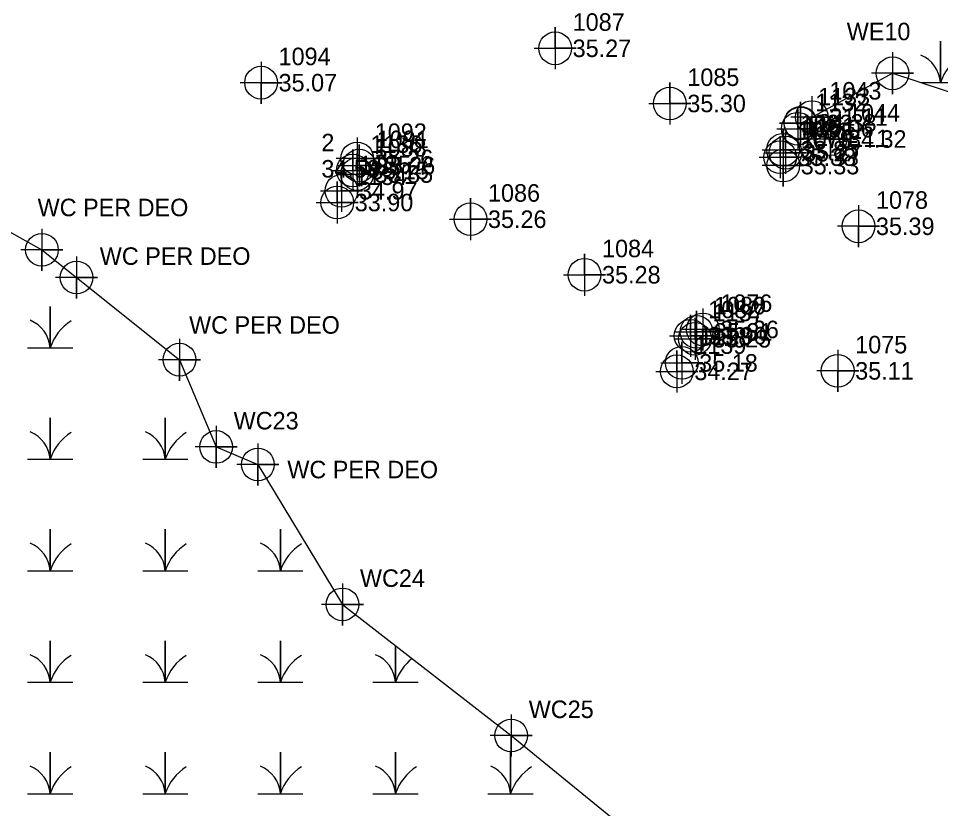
# Model space of a CAD drawing. Extents: x 2138832 to 2141061, y 149156 to 150675.
# Drawn here: x 2140515.2 to 2140647, y 149336.8 to 149449.6 of the extents above; entities that cross this region are included whole.
import ezdxf

# ---------------------------------------------------------------- set-up
doc = ezdxf.new("R2010")
doc.units = 0
for name, color, linetype in [('CTL Secondary Horizontal and Vertical Cogo Elevation', 7, 'Continuous'), ('CTL Secondary Horizontal and Vertical Cogo Number', 7, 'Continuous'), ('Exist Environmental Wetland Boundary', 7, 'Continuous'), ('Exist Environmental Wetland Boundary Cogo Number', 7, 'Continuous'), ('Exist Environmental Wetland Boundary Cogo Point CELL', 7, 'Continuous'), ('Exist Roads EOP Cogo Elevation', 7, 'Continuous'), ('Exist Roads EOP Cogo Number', 7, 'Continuous'), ('Exist Roads EOP Cogo Point CELL', 7, 'Continuous'), ('Exist Structure Major Bridge Seam Cogo Elevation', 7, 'Continuous'), ('Exist Structure Major Bridge Seam Cogo Number', 7, 'Continuous'), ('Exist Structure Major Bridge Seam Cogo Point CELL', 7, 'Continuous'), ('Exist Structure Major Bridge Seat Cogo Elevation', 7, 'Continuous'), ('Exist Structure Major Bridge Seat Cogo Number', 7, 'Continuous'), ('Exist Structure Major Bridge Seat Cogo Point CELL', 7, 'Continuous'), ('Exist Structure Major Bridge WW Cogo Elevation', 7, 'Continuous'), ('Exist Structure Major Bridge WW Cogo Number', 7, 'Continuous'), ('Exist Structure Major Bridge WW Cogo Point CELL', 7, 'Continuous'), ('Exist Structure Major Deck Tunnel Box Culvert Cogo Elevation', 7, 'Continuous'), ('Exist Structure Major Deck Tunnel Box Culvert Cogo Number', 7, 'Continuous'), ('Exist Structure Major Deck Tunnel Box Culvert Cogo Point CELL', 7, 'Continuous'), ('Exist Utilities Telephone UG FO SUE LOS C Cogo Elevation', 7, 'Continuous'), ('Exist Utilities Telephone UG FO SUE LOS C Cogo Number', 7, 'Continuous'), ('Exist Utilities Telephone UG FO SUE LOS C Cogo Point CELL', 7, 'Continuous')]:
    doc.layers.add(name, color=color, linetype=linetype)

msp = doc.modelspace()

# ---------------------------------------------------------------- linework, layer by layer
at = {"layer": 'Exist Environmental Wetland Boundary'}
msp.add_line((2140523.47, 149412.6), (2140538.17, 149400.87), dxfattribs=at)
for points in [[(2140462.13, 149440.8), (2140503.18, 149425.15), (2140518.52, 149416.56), (2140523.47, 149412.6)], [(2140626.92, 149434.6), (2140640.09, 149441.77), (2140665.85, 149433.31), (2140691.67, 149415.77), (2140722.53, 149397.21), (2140775.79, 149382.91), (2140815.44, 149353.55), (2140873.49, 149322.65), (2140932.75, 149291.76), (2140974.9, 149268.42), (2141022.6, 149236.76)], [(2140538.17, 149400.87), (2140543.42, 149388.41), (2140549.38, 149385.9)], [(2140549.38, 149385.9), (2140561.47, 149365.92)], [(2140561.47, 149365.92), (2140585.59, 149347.19)], [(2140585.59, 149347.19), (2140617.17, 149321.45), (2140653.35, 149309.39)]]:
    msp.add_lwpolyline(points, dxfattribs=at)
at = {"layer": 'Exist Environmental Wetland Boundary Cogo Point CELL'}
for points in [[(2140644.13, 149440.44), (2140646.95, 149440.44), (2140646.95, 149446.36), (2140646.95, 149440.44), (2140650.18, 149440.44)], [(2140640.09, 149444.77), (2140640.09, 149438.77), (2140640.09, 149441.77), (2140643.09, 149441.77), (2140637.09, 149441.77)], [(2140626.92, 149437.6), (2140626.92, 149431.6), (2140626.92, 149434.6), (2140629.92, 149434.6), (2140623.92, 149434.6)], [(2140518.52, 149419.56), (2140518.52, 149413.56), (2140518.52, 149416.56), (2140521.52, 149416.56), (2140515.52, 149416.56)], [(2140523.47, 149415.6), (2140523.47, 149409.6), (2140523.47, 149412.6), (2140526.47, 149412.6), (2140520.47, 149412.6)], [(2140516.47, 149402.56), (2140519.69, 149402.56), (2140519.69, 149408.48), (2140519.69, 149402.56), (2140522.92, 149402.56)], [(2140538.17, 149403.87), (2140538.17, 149397.87), (2140538.17, 149400.87), (2140541.17, 149400.87), (2140535.17, 149400.87)], [(2140516.47, 149386.65), (2140519.69, 149386.65), (2140519.69, 149392.56), (2140519.69, 149386.65), (2140522.92, 149386.65)], [(2140532.92, 149386.65), (2140536.14, 149386.65), (2140536.14, 149392.56), (2140536.14, 149386.65), (2140539.37, 149386.65)], [(2140543.42, 149391.41), (2140543.42, 149385.41), (2140543.42, 149388.41), (2140546.42, 149388.41), (2140540.42, 149388.41)], [(2140549.38, 149388.9), (2140549.38, 149382.9), (2140549.38, 149385.9), (2140552.38, 149385.9), (2140546.38, 149385.9)], [(2140516.47, 149370.73), (2140519.69, 149370.73), (2140519.69, 149376.65), (2140519.69, 149370.73), (2140522.92, 149370.73)], [(2140532.92, 149370.73), (2140536.14, 149370.73), (2140536.14, 149376.65), (2140536.14, 149370.73), (2140539.37, 149370.73)], [(2140549.37, 149370.73), (2140552.6, 149370.73), (2140552.6, 149376.65), (2140552.6, 149370.73), (2140555.82, 149370.73)], [(2140561.47, 149368.92), (2140561.47, 149362.92), (2140561.47, 149365.92), (2140564.47, 149365.92), (2140558.47, 149365.92)], [(2140516.47, 149354.81), (2140519.69, 149354.81), (2140519.69, 149360.73), (2140519.69, 149354.81), (2140522.92, 149354.81)], [(2140532.92, 149354.81), (2140536.14, 149354.81), (2140536.14, 149360.73), (2140536.14, 149354.81), (2140539.37, 149354.81)], [(2140549.37, 149354.81), (2140552.6, 149354.81), (2140552.6, 149360.73), (2140552.6, 149354.81), (2140555.82, 149354.81)], [(2140565.82, 149354.81), (2140569.05, 149354.81), (2140569.05, 149360.04)], [(2140569.05, 149360.04), (2140569.05, 149354.81), (2140572.27, 149354.81)], [(2140585.59, 149350.19), (2140585.59, 149344.19), (2140585.59, 149347.19), (2140588.59, 149347.19), (2140582.59, 149347.19)], [(2140516.47, 149338.89), (2140519.69, 149338.89), (2140519.69, 149344.81), (2140519.69, 149338.89), (2140522.92, 149338.89)], [(2140532.92, 149338.89), (2140536.14, 149338.89), (2140536.14, 149344.81), (2140536.14, 149338.89), (2140539.37, 149338.89)], [(2140549.37, 149338.89), (2140552.6, 149338.89), (2140552.6, 149344.81), (2140552.6, 149338.89), (2140555.82, 149338.89)], [(2140565.82, 149338.89), (2140569.05, 149338.89), (2140569.05, 149344.81), (2140569.05, 149338.89), (2140572.27, 149338.89)], [(2140582.27, 149338.89), (2140585.5, 149338.89), (2140585.5, 149344.81), (2140585.5, 149338.89), (2140588.72, 149338.89)]]:
    msp.add_lwpolyline(points, dxfattribs=at)
for centre in [(2140640.09, 149441.77), (2140626.92, 149434.6), (2140518.52, 149416.56), (2140523.47, 149412.6), (2140538.17, 149400.87), (2140543.42, 149388.41), (2140549.38, 149385.9), (2140561.47, 149365.92), (2140585.59, 149347.19)]:
    msp.add_circle(centre, 2.34, dxfattribs=at)
for centre, radius, start, end in [((2140642.35, 149440.11), 4.61, 4.1403, 67.535), ((2140653.79, 149438.17), 7.21, 122.1274, 161.6222), ((2140515.09, 149402.23), 4.61, 4.1403, 67.535), ((2140526.53, 149400.29), 7.21, 122.1274, 161.6222), ((2140515.09, 149386.31), 4.61, 4.1403, 67.535), ((2140526.53, 149384.37), 7.21, 122.1274, 161.6222), ((2140531.55, 149386.31), 4.61, 4.1403, 67.535), ((2140542.99, 149384.37), 7.21, 122.1274, 161.6222), ((2140515.09, 149370.4), 4.61, 4.1403, 67.535), ((2140526.53, 149368.46), 7.21, 122.1274, 161.6222), ((2140531.55, 149370.4), 4.61, 4.1403, 67.535), ((2140542.99, 149368.46), 7.21, 122.1274, 161.6222), ((2140548, 149370.4), 4.61, 4.1403, 67.535), ((2140559.44, 149368.46), 7.21, 122.1274, 161.6222), ((2140515.09, 149354.48), 4.61, 4.1403, 67.535), ((2140526.53, 149352.54), 7.21, 122.1274, 161.6222), ((2140531.55, 149354.48), 4.61, 4.1403, 67.535), ((2140542.99, 149352.54), 7.21, 122.1274, 161.6222), ((2140548, 149354.48), 4.61, 4.1403, 67.535), ((2140559.44, 149352.54), 7.21, 122.1274, 161.6222), ((2140564.45, 149354.48), 4.61, 4.1403, 67.535), ((2140575.89, 149352.54), 7.21, 128.2977, 161.6222), ((2140515.09, 149338.56), 4.61, 4.1403, 67.535), ((2140526.53, 149336.62), 7.21, 122.1274, 161.6222), ((2140531.55, 149338.56), 4.61, 4.1403, 67.535), ((2140542.99, 149336.62), 7.21, 122.1274, 161.6222), ((2140548, 149338.56), 4.61, 4.1403, 67.535), ((2140559.44, 149336.62), 7.21, 122.1274, 161.6222), ((2140564.45, 149338.56), 4.61, 4.1403, 67.535), ((2140575.89, 149336.62), 7.21, 122.1274, 161.6222), ((2140580.9, 149338.56), 4.61, 4.1403, 67.535), ((2140592.34, 149336.62), 7.21, 122.1274, 161.6222)]:
    msp.add_arc(centre, radius, start, end, dxfattribs=at)
at = {"layer": 'Exist Roads EOP Cogo Point CELL'}
for points in [[(2140549.84, 149443.43), (2140549.84, 149437.43), (2140549.84, 149440.43), (2140552.84, 149440.43), (2140546.84, 149440.43)], [(2140563.58, 149432.61), (2140563.58, 149426.61), (2140563.58, 149429.61), (2140566.58, 149429.61), (2140560.58, 149429.61)], [(2140624.47, 149431.59), (2140624.47, 149425.59), (2140624.47, 149428.59), (2140627.47, 149428.59), (2140621.47, 149428.59)], [(2140635.22, 149422.92), (2140635.22, 149416.92), (2140635.22, 149419.92), (2140638.22, 149419.92), (2140632.22, 149419.92)], [(2140612.97, 149408.19), (2140612.97, 149402.19), (2140612.97, 149405.19), (2140615.97, 149405.19), (2140609.97, 149405.19)], [(2140632.25, 149402.27), (2140632.25, 149396.27), (2140632.25, 149399.27), (2140635.25, 149399.27), (2140629.25, 149399.27)]]:
    msp.add_lwpolyline(points, dxfattribs=at)
for centre in [(2140549.84, 149440.43), (2140563.58, 149429.61), (2140624.47, 149428.59), (2140635.22, 149419.92), (2140612.97, 149405.19), (2140632.25, 149399.27)]:
    msp.add_circle(centre, 2.34, dxfattribs=at)
at = {"layer": 'Exist Structure Major Bridge Seam Cogo Point CELL'}
for points in [[(2140588.87, 149445.34), (2140594.87, 149445.34), (2140591.87, 149445.34), (2140591.87, 149448.34), (2140591.87, 149442.34)], [(2140605.26, 149437.46), (2140611.26, 149437.46), (2140608.26, 149437.46), (2140608.26, 149440.46), (2140608.26, 149434.46)], [(2140576.77, 149420.93), (2140582.77, 149420.93), (2140579.77, 149420.93), (2140579.77, 149423.93), (2140579.77, 149417.93)], [(2140593.07, 149413), (2140599.07, 149413), (2140596.07, 149413), (2140596.07, 149416), (2140596.07, 149410)]]:
    msp.add_lwpolyline(points, dxfattribs=at)
for centre in [(2140591.87, 149445.34), (2140608.26, 149437.46), (2140579.77, 149420.93), (2140596.07, 149413)]:
    msp.add_circle(centre, 2.34, dxfattribs=at)
at = {"layer": 'Exist Structure Major Bridge Seat Cogo Point CELL'}
for points in [[(2140621.44, 149430.85), (2140627.44, 149430.85), (2140624.44, 149430.85), (2140624.44, 149433.85), (2140624.44, 149427.85)], [(2140560.56, 149427.38), (2140566.56, 149427.38), (2140563.56, 149427.38), (2140563.56, 149430.38), (2140563.56, 149424.38)], [(2140608.23, 149404.29), (2140614.23, 149404.29), (2140611.23, 149404.29), (2140611.23, 149407.29), (2140611.23, 149401.29)]]:
    msp.add_lwpolyline(points, dxfattribs=at)
for centre in [(2140624.44, 149430.85), (2140563.56, 149427.38), (2140611.23, 149404.29)]:
    msp.add_circle(centre, 2.34, dxfattribs=at)
at = {"layer": 'Exist Structure Major Bridge WW Cogo Point CELL'}
for points in [[(2140623.54, 149433.85), (2140629.54, 149433.85), (2140626.54, 149433.85), (2140626.54, 149436.85), (2140626.54, 149430.85)], [(2140623.94, 149434.69), (2140629.94, 149434.69), (2140626.94, 149434.69), (2140626.94, 149437.69), (2140626.94, 149431.69)], [(2140621.8, 149430.43), (2140627.8, 149430.43), (2140624.8, 149430.43), (2140624.8, 149433.43), (2140624.8, 149427.43)], [(2140559.96, 149427.89), (2140565.96, 149427.89), (2140562.96, 149427.89), (2140562.96, 149430.89), (2140562.96, 149424.89)], [(2140558.33, 149424.99), (2140564.33, 149424.99), (2140561.33, 149424.99), (2140561.33, 149427.99), (2140561.33, 149421.99)], [(2140557.73, 149423.32), (2140563.73, 149423.32), (2140560.73, 149423.32), (2140560.73, 149426.32), (2140560.73, 149420.32)], [(2140608.86, 149403.86), (2140614.86, 149403.86), (2140611.86, 149403.86), (2140611.86, 149406.86), (2140611.86, 149400.86)], [(2140606.96, 149400.41), (2140612.96, 149400.41), (2140609.96, 149400.41), (2140609.96, 149403.41), (2140609.96, 149397.41)], [(2140606.26, 149399.2), (2140612.26, 149399.2), (2140609.26, 149399.2), (2140609.26, 149402.2), (2140609.26, 149396.2)]]:
    msp.add_lwpolyline(points, dxfattribs=at)
for centre in [(2140626.94, 149434.69), (2140626.54, 149433.85), (2140624.8, 149430.43), (2140562.96, 149427.89), (2140561.33, 149424.99), (2140560.73, 149423.32), (2140611.86, 149403.86), (2140609.96, 149400.41), (2140609.26, 149399.2)]:
    msp.add_circle(centre, 2.34, dxfattribs=at)
at = {"layer": 'Exist Structure Major Deck Tunnel Box Culvert Cogo Point CELL'}
for points in [[(2140560.86, 149428.58), (2140566.86, 149428.58), (2140563.86, 149428.58), (2140563.86, 149431.58), (2140563.86, 149425.58)], [(2140621.02, 149429.79), (2140627.02, 149429.79), (2140624.02, 149429.79), (2140624.02, 149432.79), (2140624.02, 149426.79)], [(2140609.06, 149404.84), (2140615.06, 149404.84), (2140612.06, 149404.84), (2140612.06, 149407.84), (2140612.06, 149401.84)]]:
    msp.add_lwpolyline(points, dxfattribs=at)
for centre in [(2140624.02, 149429.79), (2140563.86, 149428.58), (2140612.06, 149404.84)]:
    msp.add_circle(centre, 2.34, dxfattribs=at)
at = {"layer": 'Exist Utilities Telephone UG FO SUE LOS C Cogo Point CELL'}
for points in [[(2140628.56, 149438.52), (2140628.56, 149432.52), (2140628.56, 149435.52), (2140631.56, 149435.52), (2140625.56, 149435.52)], [(2140631.22, 149435.38), (2140631.22, 149429.38), (2140631.22, 149432.38), (2140634.22, 149432.38), (2140628.22, 149432.38)]]:
    msp.add_lwpolyline(points, dxfattribs=at)
for centre in [(2140628.56, 149435.52), (2140631.22, 149432.38)]:
    msp.add_circle(centre, 2.34, dxfattribs=at)

# ---------------------------------------------------------------- texts
at = {"layer": 'CTL Secondary Horizontal and Vertical Cogo Elevation'}
msp.add_text('34.58', height=2.5, dxfattribs=at).set_placement((2140558.46, 149426.88))
at = {"layer": 'CTL Secondary Horizontal and Vertical Cogo Number'}
msp.add_text('2', height=2.5, dxfattribs=at).set_placement((2140558.46, 149430.63))
at = {"layer": 'Exist Environmental Wetland Boundary Cogo Number'}
for s, p in [('WE10', (2140633.54, 149446.49)), ('WE11', (2140630.5, 149431.24)), ('WC PER DEO', (2140517.9, 149421.36)), ('WC PER DEO', (2140526.78, 149414.41)), ('WC PER DEO', (2140539.55, 149404.58)), ('WC23', (2140545.92, 149390.91)), ('WC PER DEO', (2140553.59, 149383.93)), ('WC24', (2140563.97, 149368.42)), ('WC25', (2140588.09, 149349.69))]:
    msp.add_text(s, height=2.5, dxfattribs=at).set_placement(p)
at = {"layer": 'Exist Roads EOP Cogo Elevation'}
for s, p in [('35.07', (2140552.34, 149439.18)), ('35.26', (2140566.08, 149428.36)), ('35.33', (2140626.97, 149427.34)), ('35.39', (2140637.72, 149418.67)), ('35.26', (2140615.47, 149403.94)), ('35.11', (2140634.75, 149398.02))]:
    msp.add_text(s, height=2.5, dxfattribs=at).set_placement(p)
at = {"layer": 'Exist Roads EOP Cogo Number'}
for s, p in [('1094', (2140552.34, 149442.93)), ('1092', (2140566.08, 149432.11)), ('1079', (2140626.97, 149431.09)), ('1078', (2140637.72, 149422.42)), ('1076', (2140615.47, 149407.69)), ('1075', (2140634.75, 149401.77))]:
    msp.add_text(s, height=2.5, dxfattribs=at).set_placement(p)
at = {"layer": 'Exist Structure Major Bridge Seam Cogo Elevation'}
for s, p in [('35.27', (2140594.37, 149444.09)), ('35.30', (2140610.76, 149436.21)), ('35.26', (2140582.27, 149419.68)), ('35.28', (2140598.57, 149411.75))]:
    msp.add_text(s, height=2.5, dxfattribs=at).set_placement(p)
at = {"layer": 'Exist Structure Major Bridge Seam Cogo Number'}
for s, p in [('1087', (2140594.37, 149447.84)), ('1085', (2140610.76, 149439.96)), ('1086', (2140582.27, 149423.43)), ('1084', (2140598.57, 149415.5))]:
    msp.add_text(s, height=2.5, dxfattribs=at).set_placement(p)
at = {"layer": 'Exist Structure Major Bridge Seat Cogo Elevation'}
for s, p in [('33.85', (2140626.94, 149429.6)), ('33.85', (2140566.06, 149426.13)), ('33.90', (2140613.73, 149403.04))]:
    msp.add_text(s, height=2.5, dxfattribs=at).set_placement(p)
at = {"layer": 'Exist Structure Major Bridge Seat Cogo Number'}
for s, p in [('1083', (2140626.94, 149433.35)), ('1088', (2140566.06, 149429.88)), ('1082', (2140613.73, 149406.79))]:
    msp.add_text(s, height=2.5, dxfattribs=at).set_placement(p)
at = {"layer": 'Exist Structure Major Bridge WW Cogo Elevation'}
for s, p in [('34.38', (2140629.44, 149433.44)), ('35.06', (2140629.04, 149432.6)), ('35.27', (2140627.3, 149429.18)), ('35.15', (2140565.46, 149426.64)), ('34.97', (2140563.83, 149423.74)), ('33.90', (2140563.23, 149422.07)), ('35.25', (2140614.36, 149402.61)), ('35.18', (2140612.46, 149399.16)), ('34.27', (2140611.76, 149397.95))]:
    msp.add_text(s, height=2.5, dxfattribs=at).set_placement(p)
at = {"layer": 'Exist Structure Major Bridge WW Cogo Number'}
for s, p in [('1133', (2140629.44, 149437.19)), ('1132', (2140629.04, 149436.35)), ('1131', (2140627.3, 149432.93)), ('1136', (2140565.46, 149430.39)), ('1135', (2140563.83, 149427.49)), ('1134', (2140563.23, 149425.82)), ('1137', (2140614.36, 149406.36)), ('1138', (2140612.46, 149402.91)), ('1139', (2140611.76, 149401.7))]:
    msp.add_text(s, height=2.5, dxfattribs=at).set_placement(p)
at = {"layer": 'Exist Structure Major Deck Tunnel Box Culvert Cogo Elevation'}
for s, p in [('35.38', (2140626.52, 149428.54)), ('35.26', (2140566.36, 149427.33)), ('35.31', (2140614.56, 149403.59))]:
    msp.add_text(s, height=2.5, dxfattribs=at).set_placement(p)
at = {"layer": 'Exist Structure Major Deck Tunnel Box Culvert Cogo Number'}
for s, p in [('1081', (2140626.52, 149432.29)), ('1091', (2140566.36, 149431.08)), ('1080', (2140614.56, 149407.34))]:
    msp.add_text(s, height=2.5, dxfattribs=at).set_placement(p)
at = {"layer": 'Exist Utilities Telephone UG FO SUE LOS C Cogo Elevation'}
for s, p in [('31.11', (2140631.06, 149434.27)), ('34.32', (2140633.72, 149431.13))]:
    msp.add_text(s, height=2.5, dxfattribs=at).set_placement(p)
at = {"layer": 'Exist Utilities Telephone UG FO SUE LOS C Cogo Number'}
for s, p in [('1043', (2140631.06, 149438.02)), ('1044', (2140633.72, 149434.88))]:
    msp.add_text(s, height=2.5, dxfattribs=at).set_placement(p)

doc.saveas('drawing.dxf')
